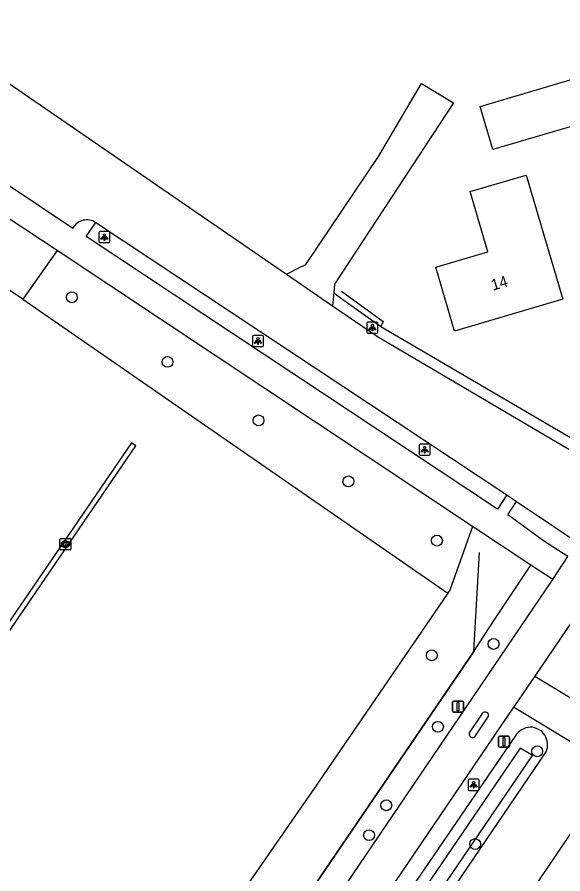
# Model space of a CAD drawing. Extents: x 157154 to 159278, y 385000 to 386650.
# Drawn here: x 158627.7 to 158676.9, y 385524.2 to 385601.5 of the extents above; entities that cross this region are included whole.
import ezdxf

# ---------------------------------------------------------------- set-up
doc = ezdxf.new("R2010")
doc.units = 0
for name, color, linetype in [('IMGEO_Boom', 7, 'Continuous'), ('IMGEO_Gemengd_bos', 7, 'Continuous'), ('IMGEO_Haag', 7, 'Continuous'), ('IMGEO_Hek', 7, 'Continuous'), ('IMGEO_Kolk', 7, 'Continuous'), ('IMGEO_Lichtpunt', 7, 'Continuous'), ('IMGEO_Loofbos', 7, 'Continuous'), ('IMGEO_Pand', 7, 'Continuous'), ('IMGEO_Pand_nummerreeks', 7, 'Continuous'), ('IMGEO_Parkeervlak_gesloten', 7, 'Continuous'), ('IMGEO_Rijbaan_lokaal_gesloten', 7, 'Continuous'), ('IMGEO_Sloot', 7, 'Continuous'), ('IMGEO_Verkeersbordpaal', 7, 'Continuous'), ('IMGEO_Voetpad_halfverhard', 7, 'Continuous'), ('IMGEO_Voetpad_open', 7, 'Continuous'), ('IMGEO_Waterloop', 7, 'Continuous')]:
    doc.layers.add(name, color=color, linetype=linetype)

msp = doc.modelspace()

# ---------------------------------------------------------------- linework, layer by layer
at = {"layer": 'IMGEO_Boom'}
for centre in [(158632.655, 385576.242), (158641.281, 385570.409), (158649.489, 385565.13), (158657.597, 385559.623), (158665.589, 385554.274), (158670.699, 385544.939), (158665.12, 385543.916), (158665.673, 385537.459), (158674.631, 385535.247), (158661.013, 385530.373), (158659.463, 385527.672), (158669.028, 385526.874)]:
    msp.add_circle(centre, 0.489, dxfattribs=at)
at = {"layer": 'IMGEO_Gemengd_bos'}
msp.add_lwpolyline([(158656.272, 385576.643), (158656.964, 385576.149), (158660.526, 385573.604), (158678.136, 385563.272)], dxfattribs=at)
at = {"layer": 'IMGEO_Haag'}
for points in [[(158668.8, 385555.554), (158666.751, 385549.798), (158666.573, 385549.538)], [(158627.646, 385483.511), (158638.822, 385500), (158668.904, 385544.272), (158670.689, 385547.011), (158674.048, 385552.067)]]:
    msp.add_lwpolyline(points, dxfattribs=at)
at = {"layer": 'IMGEO_Hek'}
for points in [[(158656.984, 385576.792), (158660.722, 385574.048), (158660.526, 385573.604)], [(158660.526, 385573.604), (158678.136, 385563.272), (158678.766, 385562.98), (158679.316, 385562.849), (158679.868, 385562.82), (158680.61, 385562.935), (158681.172, 385563.155), (158681.752, 385563.534), (158682.16, 385563.939)], [(158668.904, 385544.272), (158669.421, 385553.202)], [(158668.904, 385544.272), (158638.822, 385500), (158627.646, 385483.511)]]:
    msp.add_lwpolyline(points, dxfattribs=at)
at = {"layer": 'IMGEO_Kolk'}
for p, q in [((158631.572, 385553.526), (158631.572, 385554.378)), ((158631.647, 385554.452), (158632.499, 385554.452)), ((158632.06, 385554.232), (158632.085, 385554.232)), ((158632.573, 385554.378), (158632.573, 385553.526)), ((158632.499, 385553.452), (158631.647, 385553.452)), ((158632.083, 385553.672), (158632.058, 385553.672))]:
    msp.add_line(p, q, dxfattribs=at)
for points in [[(158631.572, 385553.526), (158631.572, 385554.378)], [(158631.647, 385554.452), (158632.499, 385554.452)], [(158631.893, 385554.152), (158632.016, 385554.152), (158632.016, 385554.001), (158632.146, 385554.152), (158632.31, 385554.152), (158632.164, 385554.001), (158632.317, 385553.752), (158632.165, 385553.752), (158632.08, 385553.916), (158632.016, 385553.849), (158632.016, 385553.752), (158631.893, 385553.752), (158631.893, 385554.152)], [(158632.573, 385554.378), (158632.573, 385553.526)], [(158632.499, 385553.452), (158631.647, 385553.452)]]:
    msp.add_lwpolyline(points, dxfattribs=at)
for centre, start, end in [((158631.649, 385554.376), 91.55205, 178.44795), ((158631.649, 385554.376), 91.55205, 178.44795), ((158632.497, 385554.376), 1.55205, 88.44795), ((158632.497, 385554.376), 1.55205, 88.44795), ((158631.649, 385553.528), 181.55205, 268.44795), ((158631.649, 385553.528), 181.55205, 268.44795), ((158632.497, 385553.528), 271.55205, 358.44795), ((158632.497, 385553.528), 271.55205, 358.44795)]:
    msp.add_arc(centre, 0.0765, start, end, dxfattribs=at)
for centre, major_axis, ratio, start_param, end_param in [((158632.059, 385553.952), (-0.387, 0.002), 0.722429, 4.712389, 7.853982), ((158632.084, 385553.952), (-0.39, 0.002), 0.717154, 1.570796, 4.712389)]:
    msp.add_ellipse(centre, major_axis=major_axis, ratio=ratio, start_param=start_param, end_param=end_param, dxfattribs=at)
at = {"layer": 'IMGEO_Lichtpunt'}
for p, q in [((158635.091, 385582.081), (158635.091, 385581.274)), ((158635.091, 385582.081), (158635.091, 385581.274)), ((158635.993, 385582.176), (158635.185, 385582.176)), ((158635.993, 385582.176), (158635.185, 385582.176)), ((158636.087, 385581.274), (158636.087, 385582.081)), ((158636.087, 385581.274), (158636.087, 385582.081)), ((158635.185, 385581.18), (158635.993, 385581.18)), ((158635.185, 385581.18), (158635.993, 385581.18)), ((158660.17, 385574.002), (158659.362, 385574.002)), ((158660.17, 385574.002), (158659.362, 385574.002)), ((158659.268, 385573.907), (158659.268, 385573.1)), ((158659.268, 385573.907), (158659.268, 385573.1)), ((158660.264, 385573.1), (158660.264, 385573.907)), ((158660.264, 385573.1), (158660.264, 385573.907)), ((158648.949, 385572.701), (158648.949, 385571.894)), ((158648.949, 385572.701), (158648.949, 385571.894)), ((158649.851, 385572.796), (158649.043, 385572.796)), ((158649.851, 385572.796), (158649.043, 385572.796)), ((158649.945, 385571.894), (158649.945, 385572.701)), ((158649.945, 385571.894), (158649.945, 385572.701)), ((158659.362, 385573.006), (158660.17, 385573.006)), ((158659.362, 385573.006), (158660.17, 385573.006)), ((158649.043, 385571.8), (158649.851, 385571.8)), ((158649.043, 385571.8), (158649.851, 385571.8)), ((158663.977, 385562.878), (158663.977, 385562.071)), ((158663.977, 385562.878), (158663.977, 385562.071)), ((158664.879, 385562.973), (158664.071, 385562.973)), ((158664.879, 385562.973), (158664.071, 385562.973)), ((158664.973, 385562.071), (158664.973, 385562.878)), ((158664.973, 385562.071), (158664.973, 385562.878)), ((158664.071, 385561.977), (158664.879, 385561.977)), ((158664.071, 385561.977), (158664.879, 385561.977)), ((158668.396, 385532.622), (158668.396, 385531.815)), ((158668.396, 385532.622), (158668.396, 385531.815)), ((158669.298, 385532.717), (158668.49, 385532.717)), ((158669.298, 385532.717), (158668.49, 385532.717)), ((158669.392, 385531.815), (158669.392, 385532.622)), ((158669.392, 385531.815), (158669.392, 385532.622)), ((158668.49, 385531.721), (158669.298, 385531.721)), ((158668.49, 385531.721), (158669.298, 385531.721))]:
    msp.add_line(p, q, dxfattribs=at)
for points in [[(158635.465, 385581.745), (158635.504, 385581.717), (158635.316, 385581.455), (158635.278, 385581.482), (158635.465, 385581.745)], [(158635.567, 385581.697), (158635.614, 385581.697), (158635.614, 385581.375), (158635.567, 385581.375), (158635.567, 385581.697)], [(158635.677, 385581.717), (158635.715, 385581.744), (158635.902, 385581.482), (158635.863, 385581.454), (158635.677, 385581.717)], [(158659.642, 385573.571), (158659.681, 385573.543), (158659.493, 385573.281), (158659.455, 385573.308), (158659.642, 385573.571)], [(158659.744, 385573.523), (158659.791, 385573.523), (158659.791, 385573.201), (158659.744, 385573.201), (158659.744, 385573.523)], [(158659.854, 385573.543), (158659.892, 385573.57), (158660.079, 385573.308), (158660.04, 385573.28), (158659.854, 385573.543)], [(158649.323, 385572.365), (158649.362, 385572.337), (158649.174, 385572.075), (158649.136, 385572.102), (158649.323, 385572.365)], [(158649.425, 385572.317), (158649.472, 385572.317), (158649.472, 385571.995), (158649.425, 385571.995), (158649.425, 385572.317)], [(158649.535, 385572.337), (158649.573, 385572.364), (158649.76, 385572.102), (158649.721, 385572.074), (158649.535, 385572.337)], [(158664.351, 385562.542), (158664.39, 385562.514), (158664.202, 385562.252), (158664.164, 385562.279), (158664.351, 385562.542)], [(158664.453, 385562.494), (158664.5, 385562.494), (158664.5, 385562.172), (158664.453, 385562.172), (158664.453, 385562.494)], [(158664.563, 385562.514), (158664.601, 385562.541), (158664.788, 385562.279), (158664.749, 385562.251), (158664.563, 385562.514)], [(158668.77, 385532.286), (158668.809, 385532.258), (158668.621, 385531.996), (158668.583, 385532.023), (158668.77, 385532.286)], [(158668.872, 385532.238), (158668.919, 385532.238), (158668.919, 385531.916), (158668.872, 385531.916), (158668.872, 385532.238)], [(158668.982, 385532.258), (158669.02, 385532.285), (158669.207, 385532.023), (158669.168, 385531.995), (158668.982, 385532.258)]]:
    msp.add_lwpolyline(points, dxfattribs=at)
for centre in [(158635.59, 385581.879), (158659.767, 385573.705), (158649.448, 385572.499), (158664.476, 385562.676), (158668.895, 385532.42)]:
    msp.add_circle(centre, 0.0994, dxfattribs=at)
for centre, start, end in [((158635.185, 385582.081), 90, 180), ((158635.185, 385582.081), 90, 180), ((158635.993, 385582.081), 0, 90), ((158635.993, 385582.081), 0, 90), ((158635.185, 385581.274), 180, 270), ((158635.185, 385581.274), 180, 270), ((158635.993, 385581.274), 270, 0), ((158635.993, 385581.274), 270, 360), ((158659.362, 385573.907), 90, 180), ((158659.362, 385573.907), 90, 180), ((158660.17, 385573.907), 0, 90), ((158660.17, 385573.907), 0, 90), ((158649.043, 385572.701), 90, 180), ((158649.043, 385572.701), 90, 180), ((158649.851, 385572.701), 0, 90), ((158649.851, 385572.701), 0, 90), ((158659.362, 385573.1), 180, 270), ((158659.362, 385573.1), 180, 270), ((158660.17, 385573.1), 270, 0), ((158660.17, 385573.1), 270, 360), ((158649.043, 385571.894), 180, 270), ((158649.043, 385571.894), 180, 270), ((158649.851, 385571.894), 270, 0), ((158649.851, 385571.894), 270, 360), ((158664.071, 385562.878), 90, 180), ((158664.071, 385562.878), 90, 180), ((158664.879, 385562.878), 0, 90), ((158664.879, 385562.878), 0, 90), ((158664.071, 385562.071), 180, 270), ((158664.071, 385562.071), 180, 270), ((158664.879, 385562.071), 270, 0), ((158664.879, 385562.071), 270, 360), ((158668.49, 385532.622), 90, 180), ((158668.49, 385532.622), 90, 180), ((158669.298, 385532.622), 0, 90), ((158669.298, 385532.622), 0, 90), ((158668.49, 385531.815), 180, 270), ((158668.49, 385531.815), 180, 270), ((158669.298, 385531.815), 270, 0), ((158669.298, 385531.815), 270, 360)]:
    msp.add_arc(centre, 0.0946, start, end, dxfattribs=at)
at = {"layer": 'IMGEO_Loofbos'}
for points in [[(158672.636, 385536.613), (158647.655, 385500), (158624.577, 385466.175), (158601.84, 385432.273), (158563.335, 385375.618), (158530.805, 385326.778), (158527.65, 385322.353), (158526.708, 385322.254), (158526.494, 385322.064), (158526.115, 385320.49)], [(158572.519, 385383.258), (158590.753, 385410.188), (158601.359, 385425.531), (158630.519, 385469.342), (158651.568, 385500), (158675.44, 385535.194)]]:
    msp.add_lwpolyline(points, dxfattribs=at)
for centre, radius, start, end in [((158674.155, 385535.626), 1.812, 94.63148, 147.00101), ((158673.955, 385535.821), 1.612, 337.12473, 88.0658)]:
    msp.add_arc(centre, radius, start, end, dxfattribs=at)
at = {"layer": 'IMGEO_Pand'}
for points in [[(158678.121, 385596.021), (158679.268, 385592.117), (158670.624, 385589.576), (158669.477, 385593.48), (158678.121, 385596.021)], [(158673.631, 385587.28), (158676.929, 385576.066), (158667.174, 385573.198), (158665.475, 385578.977), (158670.184, 385580.361), (158668.586, 385585.797), (158673.631, 385587.28)]]:
    msp.add_lwpolyline(points, dxfattribs=at)
at = {"layer": 'IMGEO_Parkeervlak_gesloten'}
for points in [[(158628.234, 385576.065), (158666.573, 385549.538)], [(158638.024, 385563.116), (158601.537, 385509.707), (158601.97, 385509.43), (158638.427, 385562.839), (158638.024, 385563.116)], [(158666.573, 385549.538), (158654.558, 385531.992), (158645.594, 385519.031)]]:
    msp.add_lwpolyline(points, dxfattribs=at)
at = {"layer": 'IMGEO_Rijbaan_lokaal_gesloten'}
for points in [[(158619.061, 385601.834), (158619.092, 385600.968), (158652.012, 385578.342)], [(158652.012, 385578.342), (158653.198, 385578.932), (158653.77, 385579.216), (158660.314, 385588.96), (158664.18, 385595.562), (158667.091, 385593.81), (158656.343, 385577.425), (158656.272, 385576.643)], [(158624.046, 385588.306), (158632.749, 385582.498)], [(158631.313, 385580.459), (158622.628, 385586.199)], [(158634.799, 385582.997), (158671.9, 385558.406)], [(158628.234, 385576.065), (158619.585, 385581.801)], [(158631.313, 385580.459), (158628.234, 385576.065)], [(158652.012, 385578.342), (158656.167, 385575.487)], [(158656.272, 385576.643), (158656.167, 385575.487)], [(158656.167, 385575.487), (158660.224, 385572.698), (158677.492, 385562.542)], [(158671.9, 385558.406), (158672.77, 385557.816)], [(158672.77, 385557.816), (158676.126, 385555.54), (158678.276, 385554.103)], [(158682.812, 385554.392), (158674.409, 385542.043)], [(158676.028, 385550.752), (158677.405, 385552.827)], [(158531.86, 385337.675), (158581.034, 385410.481), (158671.908, 385544.668), (158676.028, 385550.752)], [(158674.409, 385542.043), (158672.575, 385539.348), (158672.498, 385539.233)], [(158672.498, 385539.233), (158554.662, 385365.305), (158526.59, 385323.554)], [(158669.671, 385538.655), (158668.544, 385536.997)], [(158669.06, 385536.646), (158670.194, 385538.346)]]:
    msp.add_lwpolyline(points, dxfattribs=at)
for centre, radius, start, end in [((158634.005, 385581.797), 1.438, 56.50827, 150.85289), ((158669.929, 385538.494), 0.304, 330.79894, 148.04999), ((158668.792, 385536.807), 0.313, 142.58167, 328.9687)]:
    msp.add_arc(centre, radius, start, end, dxfattribs=at)
at = {"layer": 'IMGEO_Sloot'}
msp.add_lwpolyline([(158678.392, 385528.949), (158658.835, 385500), (158623.181, 385446.733), (158624.93, 385445.662), (158661.45, 385500), (158680.176, 385526.77)], dxfattribs=at)
at = {"layer": 'IMGEO_Verkeersbordpaal'}
for p, q in [((158666.99, 385538.872), (158666.99, 385539.672)), ((158666.99, 385539.672), (158666.99, 385538.872)), ((158667.09, 385539.772), (158667.88, 385539.772)), ((158667.88, 385539.772), (158667.09, 385539.772)), ((158667.98, 385539.672), (158667.98, 385538.872)), ((158667.98, 385538.872), (158667.98, 385539.672)), ((158667.88, 385538.772), (158667.09, 385538.772)), ((158667.09, 385538.772), (158667.88, 385538.772)), ((158671.144, 385535.708), (158671.144, 385536.508)), ((158671.144, 385536.508), (158671.144, 385535.708)), ((158671.244, 385536.608), (158672.034, 385536.608)), ((158672.034, 385536.608), (158671.244, 385536.608)), ((158672.134, 385536.508), (158672.134, 385535.708)), ((158672.134, 385535.708), (158672.134, 385536.508)), ((158672.034, 385535.608), (158671.244, 385535.608)), ((158671.244, 385535.608), (158672.034, 385535.608))]:
    msp.add_line(p, q, dxfattribs=at)
for points in [[(158667.41, 385539.647), (158667.56, 385539.647), (158667.56, 385538.897), (158667.41, 385538.897), (158667.41, 385539.647)], [(158671.564, 385536.483), (158671.714, 385536.483), (158671.714, 385535.733), (158671.564, 385535.733), (158671.564, 385536.483)]]:
    msp.add_lwpolyline(points, dxfattribs=at)
for centre, start, end in [((158667.09, 385539.672), 90, 180), ((158667.09, 385539.672), 90, 180), ((158667.88, 385539.672), 0, 90), ((158667.88, 385539.672), 360, 90), ((158667.09, 385538.872), 180, 270), ((158667.09, 385538.872), 180, 270), ((158667.88, 385538.872), 270, 0), ((158667.88, 385538.872), 270, 0), ((158671.244, 385536.508), 90, 180), ((158671.244, 385536.508), 90, 180), ((158672.034, 385536.508), 0, 90), ((158672.034, 385536.508), 360, 90), ((158671.244, 385535.708), 180, 270), ((158671.244, 385535.708), 180, 270), ((158672.034, 385535.708), 270, 0), ((158672.034, 385535.708), 270, 0)]:
    msp.add_arc(centre, 0.1, start, end, dxfattribs=at)
at = {"layer": 'IMGEO_Voetpad_halfverhard'}
for points in [[(158674.409, 385542.043), (158702.865, 385524.759)], [(158702.316, 385520.276), (158702.143, 385520.922), (158701.752, 385521.463), (158672.498, 385539.233)]]:
    msp.add_lwpolyline(points, dxfattribs=at)
at = {"layer": 'IMGEO_Voetpad_open'}
for points in [[(158671.9, 385558.406), (158671.034, 385557.11), (158633.928, 385581.732), (158634.799, 385582.997)], [(158668.8, 385555.554), (158631.313, 385580.459)], [(158677.405, 385552.827), (158675.297, 385554.195), (158671.969, 385556.609), (158672.77, 385557.816)], [(158674.048, 385552.067), (158668.8, 385555.554)], [(158676.028, 385550.752), (158674.048, 385552.067)]]:
    msp.add_lwpolyline(points, dxfattribs=at)
at = {"layer": 'IMGEO_Waterloop'}
msp.add_lwpolyline([(158528.132, 385321.562), (158528.939, 385321.095), (158542.612, 385340.883), (158606.646, 385435.575), (158674.204, 385534.853), (158673.1, 385535.532), (158596.54, 385423.091), (158528.132, 385321.562)], dxfattribs=at)

# ---------------------------------------------------------------- texts
at = {"layer": 'IMGEO_Pand_nummerreeks'}
msp.add_text('14', height=1, rotation=16.3835, dxfattribs=at).set_placement((158670.636, 385576.842))

doc.saveas('drawing.dxf')
